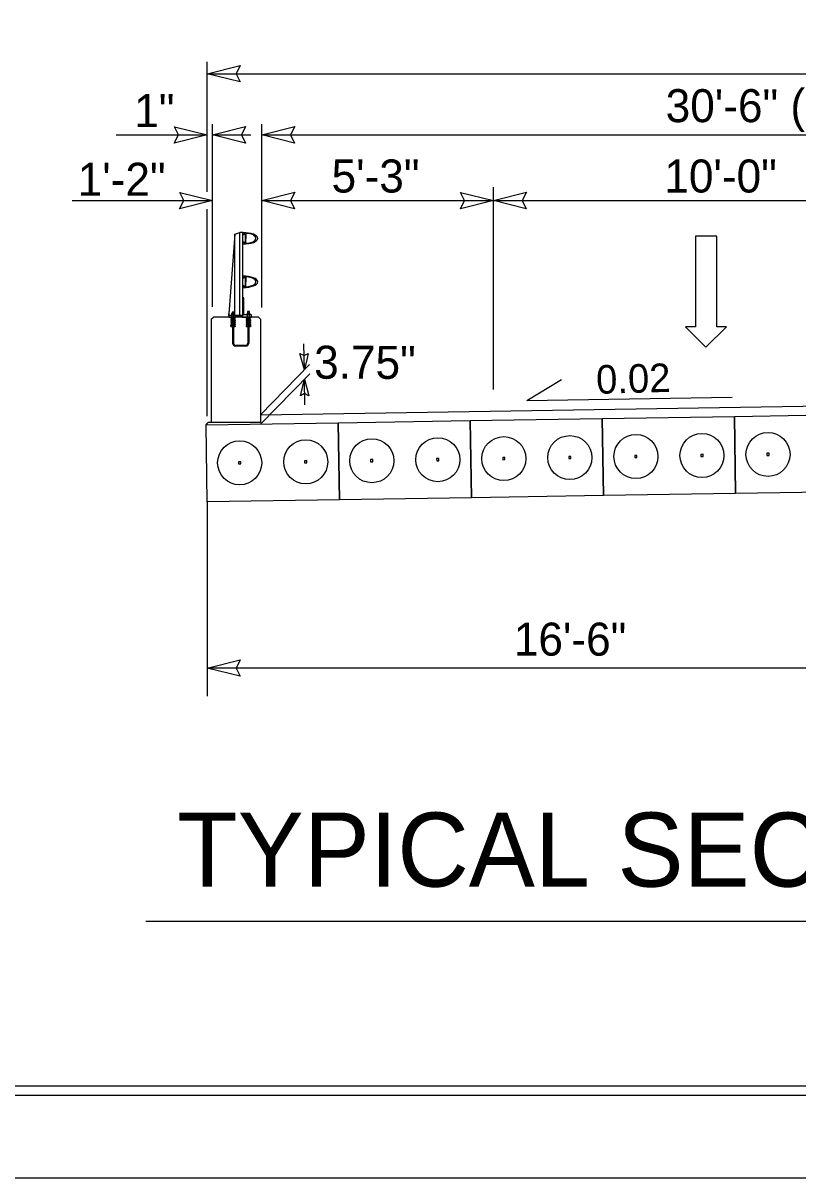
# Model space of a CAD drawing. Extents: x 573980 to 574178, y -53449 to -53334.
# Drawn here: x 574063.55 to 574085.55, y -53449.04 to -53416.26 of the extents above; entities that cross this region are included whole.
import ezdxf

# ---------------------------------------------------------------- set-up
doc = ezdxf.new("R2010")
doc.units = 0
for name, color, linetype in [('Old_Level_1', 7, 'Continuous'), ('Old_Level_11', 7, 'Continuous'), ('Old_Level_3', 7, 'Continuous'), ('Prop Dimension Text', 7, 'Continuous'), ('Prop Lane Arrow CELL', 7, 'Continuous'), ('Sheet Plot Border Inside CELL', 7, 'Continuous'), ('Sheet Plot Border Outside CELL', 7, 'Continuous'), ('Sheet Typical CELL', 7, 'Continuous'), ('Typical Arrow Superelevation CELL', 7, 'Continuous'), ('Typical Berm Information CELL', 7, 'Continuous'), ('Typical Bridge Rail Two Bar CELL', 7, 'Continuous'), ('Typical Terminator CELL', 7, 'Continuous')]:
    doc.layers.add(name, color=color, linetype=linetype)

# ---------------------------------------------------------------- blocks, each defined once
blk = doc.blocks.new('TERMINATOR')
at = {"layer": 'Typical Terminator CELL'}
blk.add_lwpolyline([(-0.469, 0.081), (0, 0), (-0.471, -0.083), (-0.411, 0)], close=True, dxfattribs=at)
blk = doc.blocks.new('Lane Arrow Through')
at = {"layer": 'Prop Lane Arrow CELL'}
for p, q in [((-3.15, 1.6), (-3.15, 3.1)), ((-3.15, 3.1), (0, 0)), ((-17.15, 1.6), (-3.15, 1.6)), ((-17.15, -1.7), (-17.15, 1.6)), ((0, 0), (-3.15, -3.2)), ((-3.15, -1.7), (-17.15, -1.7)), ((-3.15, -3.2), (-3.15, -1.7))]:
    blk.add_line(p, q, dxfattribs=at)

msp = doc.modelspace()

# ---------------------------------------------------------------- linework, layer by layer
at = {"layer": 'Old_Level_1'}
for p, q in [((574070.29, -53427.378), (574108.44, -53426.767)), ((574083.745, -53427.423), (574087.495, -53427.363)), ((574068.747, -53427.663), (574072.497, -53427.603)), ((574068.782, -53429.85), (574068.747, -53427.663)), ((574072.497, -53427.603), (574076.246, -53427.543)), ((574072.497, -53427.603), (574072.532, -53429.79)), ((574072.532, -53429.79), (574072.497, -53427.603)), ((574076.246, -53427.543), (574079.996, -53427.483)), ((574076.246, -53427.543), (574076.281, -53429.73)), ((574076.281, -53429.73), (574076.246, -53427.543)), ((574079.996, -53427.483), (574083.745, -53427.423)), ((574079.996, -53427.483), (574080.031, -53429.67)), ((574080.031, -53429.67), (574079.996, -53427.483)), ((574083.745, -53427.423), (574083.78, -53429.61)), ((574083.78, -53429.61), (574083.745, -53427.423)), ((574069.702, -53428.71), (574069.669, -53428.71)), ((574069.669, -53428.71), (574069.67, -53428.772)), ((574069.731, -53428.709), (574069.702, -53428.71)), ((574069.732, -53428.771), (574069.731, -53428.709)), ((574071.576, -53428.68), (574071.544, -53428.68)), ((574071.544, -53428.68), (574071.545, -53428.742)), ((574071.606, -53428.679), (574071.576, -53428.68)), ((574071.607, -53428.741), (574071.606, -53428.679)), ((574073.451, -53428.65), (574073.419, -53428.65)), ((574073.419, -53428.65), (574073.42, -53428.712)), ((574073.42, -53428.712), (574073.482, -53428.711)), ((574073.481, -53428.649), (574073.451, -53428.65)), ((574073.482, -53428.711), (574073.481, -53428.649)), ((574075.326, -53428.62), (574075.294, -53428.62)), ((574075.294, -53428.62), (574075.295, -53428.682)), ((574075.295, -53428.682), (574075.357, -53428.681)), ((574075.356, -53428.619), (574075.326, -53428.62)), ((574075.357, -53428.681), (574075.356, -53428.619)), ((574077.201, -53428.59), (574077.168, -53428.59)), ((574077.168, -53428.59), (574077.169, -53428.652)), ((574077.169, -53428.652), (574077.231, -53428.651)), ((574077.23, -53428.589), (574077.201, -53428.59)), ((574077.231, -53428.651), (574077.23, -53428.589)), ((574079.075, -53428.56), (574079.043, -53428.56)), ((574079.043, -53428.56), (574079.044, -53428.622)), ((574079.044, -53428.622), (574079.106, -53428.621)), ((574079.105, -53428.559), (574079.075, -53428.56)), ((574079.106, -53428.621), (574079.105, -53428.559)), ((574080.95, -53428.53), (574080.918, -53428.53)), ((574080.918, -53428.53), (574080.919, -53428.592)), ((574080.919, -53428.592), (574080.981, -53428.591)), ((574080.98, -53428.529), (574080.95, -53428.53)), ((574080.981, -53428.591), (574080.98, -53428.529)), ((574082.825, -53428.5), (574082.793, -53428.5)), ((574082.793, -53428.5), (574082.794, -53428.562)), ((574082.794, -53428.562), (574082.856, -53428.561)), ((574082.855, -53428.499), (574082.825, -53428.5)), ((574082.856, -53428.561), (574082.855, -53428.499)), ((574084.7, -53428.47), (574084.668, -53428.47)), ((574084.668, -53428.47), (574084.669, -53428.532)), ((574084.669, -53428.532), (574084.73, -53428.531)), ((574084.729, -53428.469), (574084.7, -53428.47)), ((574084.73, -53428.531), (574084.729, -53428.469)), ((574069.67, -53428.772), (574069.732, -53428.771)), ((574071.545, -53428.742), (574071.607, -53428.741)), ((574080.031, -53429.67), (574076.281, -53429.73)), ((574083.78, -53429.61), (574080.031, -53429.67)), ((574087.53, -53429.55), (574083.78, -53429.61)), ((574072.532, -53429.79), (574068.782, -53429.85)), ((574076.281, -53429.73), (574072.532, -53429.79)), ((574067.039, -53441.751), (574110.919, -53441.751))]:
    msp.add_line(p, q, dxfattribs=at)
for centre in [(574073.452, -53428.682), (574075.326, -53428.652), (574077.201, -53428.622), (574079.076, -53428.592), (574080.951, -53428.562), (574082.825, -53428.532), (574084.7, -53428.502), (574069.702, -53428.742), (574071.577, -53428.712)]:
    msp.add_circle(centre, 0.625, dxfattribs=at)
at = {"layer": 'Prop Dimension Text'}
for p, q in [((574068.782, -53421.051), (574068.782, -53417.355)), ((574068.782, -53417.697), (574110.032, -53417.697)), ((574068.932, -53424.312), (574068.932, -53419.126)), ((574070.33, -53424.334), (574070.33, -53419.126)), ((574066.198, -53419.434), (574068.782, -53419.434)), ((574068.932, -53419.434), (574070.018, -53419.434)), ((574070.33, -53419.434), (574108.485, -53419.434)), ((574076.903, -53426.661), (574076.903, -53420.92)), ((574064.951, -53421.299), (574068.932, -53421.299)), ((574070.33, -53421.299), (574108.485, -53421.299)), ((574068.782, -53427.421), (574068.782, -53421.545)), ((574071.538, -53426.103), (574071.526, -53425.367)), ((574070.29, -53427.378), (574071.685, -53425.953)), ((574070.295, -53427.639), (574071.689, -53426.214)), ((574071.554, -53427.098), (574071.542, -53426.368)), ((574068.782, -53429.85), (574068.782, -53435.367)), ((574089.403, -53434.565), (574068.782, -53434.565))]:
    msp.add_line(p, q, dxfattribs=at)
at = {"layer": 'Sheet Plot Border Inside CELL'}
msp.add_lwpolyline([(574155.747, -53336.331), (573981.441, -53336.331), (573981.441, -53446.688), (574155.747, -53446.688)], close=True, dxfattribs=at)
at = {"layer": 'Sheet Plot Border Outside CELL'}
msp.add_lwpolyline([(574156.218, -53333.982), (573980.081, -53333.982), (573980.081, -53449.036), (574156.218, -53449.036)], close=True, dxfattribs=at)
at = {"layer": 'Sheet Typical CELL'}
msp.add_lwpolyline([(574154.44, -53336.597), (573997.548, -53336.597), (573997.548, -53446.421), (574154.44, -53446.421)], close=True, dxfattribs=at)
at = {"layer": 'Typical Arrow Superelevation CELL'}
for q in [(574078.835, -53426.38), (574083.68, -53426.875)]:
    msp.add_line((574077.854, -53426.968), q, dxfattribs=at)
at = {"layer": 'Typical Bridge Rail Two Bar CELL'}
for p, q in [((574069.56, -53422.249), (574069.396, -53424.51)), ((574069.56, -53422.249), (574069.702, -53422.203)), ((574069.56, -53424.557), (574069.56, -53422.249)), ((574069.796, -53422.203), (574069.702, -53422.203)), ((574069.702, -53424.557), (574069.702, -53422.203)), ((574069.796, -53424.557), (574069.796, -53422.203)), ((574069.875, -53422.242), (574069.875, -53422.37)), ((574069.875, -53422.498), (574069.875, -53422.37)), ((574069.56, -53423.33), (574069.555, -53423.33)), ((574069.875, -53423.476), (574069.875, -53423.604)), ((574069.875, -53423.731), (574069.875, -53423.604)), ((574069.4, -53424.484), (574069.4, -53424.443)), ((574069.977, -53424.45), (574069.923, -53424.45)), ((574069.923, -53424.45), (574069.923, -53424.494)), ((574069.977, -53424.494), (574069.977, -53424.45)), ((574068.897, -53424.665), (574068.958, -53424.604)), ((574068.897, -53424.665), (574068.897, -53427.596)), ((574070.234, -53424.604), (574068.958, -53424.604)), ((574069.396, -53424.557), (574069.396, -53424.51)), ((574069.575, -53424.65), (574069.45, -53424.65)), ((574069.575, -53424.663), (574069.45, -53424.663)), ((574069.502, -53424.705), (574069.45, -53424.705)), ((574069.502, -53424.719), (574069.45, -53424.719)), ((574069.502, -53424.761), (574069.45, -53424.761)), ((574069.502, -53424.775), (574069.45, -53424.775)), ((574069.502, -53424.678), (574069.477, -53424.678)), ((574069.502, -53424.691), (574069.477, -53424.691)), ((574069.502, -53424.733), (574069.477, -53424.733)), ((574069.502, -53424.747), (574069.477, -53424.747)), ((574069.486, -53424.661), (574069.486, -53424.557)), ((574069.541, -53424.462), (574069.487, -53424.462)), ((574069.487, -53424.462), (574069.487, -53424.506)), ((574069.523, -53424.677), (574069.502, -53424.677)), ((574069.502, -53424.677), (574069.502, -53425.341)), ((574069.523, -53424.677), (574069.523, -53425.341)), ((574069.547, -53424.678), (574069.523, -53424.678)), ((574069.547, -53424.691), (574069.523, -53424.691)), ((574069.575, -53424.705), (574069.523, -53424.705)), ((574069.575, -53424.719), (574069.523, -53424.719)), ((574069.547, -53424.733), (574069.523, -53424.733)), ((574069.547, -53424.747), (574069.523, -53424.747)), ((574069.575, -53424.761), (574069.523, -53424.761)), ((574069.575, -53424.775), (574069.523, -53424.775)), ((574069.54, -53424.661), (574069.54, -53424.557)), ((574069.541, -53424.506), (574069.541, -53424.462)), ((574070.011, -53424.65), (574069.885, -53424.65)), ((574070.011, -53424.663), (574069.885, -53424.663)), ((574069.938, -53424.705), (574069.885, -53424.705)), ((574069.938, -53424.719), (574069.885, -53424.719)), ((574069.938, -53424.761), (574069.885, -53424.761)), ((574069.938, -53424.775), (574069.885, -53424.775)), ((574069.938, -53424.678), (574069.913, -53424.678)), ((574069.938, -53424.691), (574069.913, -53424.691)), ((574069.938, -53424.733), (574069.913, -53424.733)), ((574069.938, -53424.747), (574069.913, -53424.747)), ((574069.92, -53424.65), (574069.92, -53424.545)), ((574069.938, -53424.677), (574069.938, -53425.341)), ((574069.959, -53424.678), (574069.938, -53424.678)), ((574069.959, -53424.677), (574069.959, -53425.341)), ((574069.983, -53424.678), (574069.959, -53424.678)), ((574069.983, -53424.691), (574069.959, -53424.691)), ((574070.011, -53424.705), (574069.959, -53424.705)), ((574070.011, -53424.719), (574069.959, -53424.719)), ((574069.983, -53424.733), (574069.959, -53424.733)), ((574069.983, -53424.747), (574069.959, -53424.747)), ((574070.011, -53424.761), (574069.959, -53424.761)), ((574070.011, -53424.775), (574069.959, -53424.775)), ((574069.979, -53424.65), (574069.979, -53424.545)), ((574070.234, -53424.604), (574070.295, -53424.665)), ((574070.295, -53424.665), (574070.295, -53427.596)), ((574069.502, -53424.816), (574069.45, -53424.816)), ((574069.502, -53424.83), (574069.45, -53424.83)), ((574069.502, -53424.872), (574069.45, -53424.872)), ((574069.502, -53424.885), (574069.45, -53424.885)), ((574069.502, -53424.789), (574069.477, -53424.789)), ((574069.502, -53424.802), (574069.477, -53424.802)), ((574069.502, -53424.844), (574069.477, -53424.844)), ((574069.502, -53424.858), (574069.477, -53424.858)), ((574069.547, -53424.789), (574069.523, -53424.789)), ((574069.547, -53424.802), (574069.523, -53424.802)), ((574069.575, -53424.816), (574069.523, -53424.816)), ((574069.575, -53424.83), (574069.523, -53424.83)), ((574069.547, -53424.844), (574069.523, -53424.844)), ((574069.547, -53424.858), (574069.523, -53424.858)), ((574069.575, -53424.872), (574069.523, -53424.872)), ((574069.575, -53424.885), (574069.523, -53424.885)), ((574069.938, -53424.816), (574069.885, -53424.816)), ((574069.938, -53424.83), (574069.885, -53424.83)), ((574069.938, -53424.872), (574069.885, -53424.872)), ((574069.938, -53424.885), (574069.885, -53424.885)), ((574069.938, -53424.789), (574069.913, -53424.789)), ((574069.938, -53424.802), (574069.913, -53424.802)), ((574069.938, -53424.844), (574069.913, -53424.844)), ((574069.938, -53424.858), (574069.913, -53424.858)), ((574069.983, -53424.789), (574069.959, -53424.789)), ((574069.983, -53424.802), (574069.959, -53424.802)), ((574070.011, -53424.816), (574069.959, -53424.816)), ((574070.011, -53424.83), (574069.959, -53424.83)), ((574069.983, -53424.844), (574069.959, -53424.844)), ((574069.983, -53424.858), (574069.959, -53424.858)), ((574070.011, -53424.872), (574069.959, -53424.872)), ((574070.011, -53424.885), (574069.959, -53424.885)), ((574069.871, -53425.407), (574069.59, -53425.407)), ((574069.871, -53425.428), (574069.59, -53425.428)), ((574068.747, -53427.663), (574068.808, -53427.596)), ((574068.909, -53427.596), (574068.808, -53427.596)), ((574070.295, -53427.596), (574068.909, -53427.596))]:
    msp.add_line(p, q, dxfattribs=at)
for points in [[(574069.796, -53422.533), (574069.796, -53422.472), (574069.822, -53422.472), (574069.822, -53422.482), (574069.819, -53422.482), (574069.819, -53422.507), (574069.86, -53422.507), (574069.865, -53422.468), (574069.865, -53422.37), (574069.865, -53422.271), (574069.86, -53422.232), (574069.819, -53422.232), (574069.819, -53422.257), (574069.822, -53422.257), (574069.822, -53422.268), (574069.796, -53422.268), (574069.796, -53422.206)], [(574069.796, -53423.767), (574069.796, -53423.706), (574069.822, -53423.706), (574069.822, -53423.716), (574069.819, -53423.716), (574069.819, -53423.741), (574069.86, -53423.741), (574069.865, -53423.702), (574069.865, -53423.604), (574069.865, -53423.505), (574069.86, -53423.466), (574069.819, -53423.466), (574069.819, -53423.491), (574069.822, -53423.491), (574069.822, -53423.502), (574069.796, -53423.502), (574069.796, -53423.441)], [(574070.038, -53424.604), (574070.038, -53424.545), (574069.82, -53424.545), (574069.82, -53424.062), (574069.796, -53424.062), (574069.796, -53424.557), (574069.407, -53424.557), (574069.407, -53424.522), (574069.396, -53424.522), (574069.396, -53424.604), (574069.583, -53424.604), (574069.583, -53424.572), (574069.773, -53424.572), (574069.773, -53424.604), (574070.038, -53424.604)], [(574069.45, -53424.65), (574069.45, -53424.663), (574069.477, -53424.678), (574069.477, -53424.691), (574069.45, -53424.705), (574069.45, -53424.719), (574069.477, -53424.733), (574069.477, -53424.747), (574069.45, -53424.761), (574069.45, -53424.775), (574069.477, -53424.789), (574069.477, -53424.802), (574069.45, -53424.816), (574069.45, -53424.83), (574069.477, -53424.844), (574069.477, -53424.858), (574069.45, -53424.872), (574069.45, -53424.885)], [(574069.567, -53424.558), (574069.567, -53424.547), (574069.514, -53424.547), (574069.46, -53424.547), (574069.46, -53424.558)], [(574069.553, -53424.547), (574069.553, -53424.513), (574069.547, -53424.506), (574069.481, -53424.506), (574069.474, -53424.513), (574069.474, -53424.547), (574069.553, -53424.547), (574069.527, -53424.547), (574069.527, -53424.513), (574069.534, -53424.506), (574069.527, -53424.513), (574069.521, -53424.506), (574069.507, -53424.506), (574069.5, -53424.513), (574069.5, -53424.547), (574069.5, -53424.513), (574069.494, -53424.506)], [(574069.575, -53424.65), (574069.575, -53424.663), (574069.548, -53424.678), (574069.548, -53424.691), (574069.575, -53424.705), (574069.575, -53424.719), (574069.548, -53424.733), (574069.548, -53424.747), (574069.575, -53424.761), (574069.575, -53424.775), (574069.548, -53424.789), (574069.548, -53424.802), (574069.575, -53424.816), (574069.575, -53424.83), (574069.548, -53424.844), (574069.548, -53424.858), (574069.575, -53424.872), (574069.575, -53424.885)], [(574069.885, -53424.65), (574069.885, -53424.663), (574069.913, -53424.678), (574069.913, -53424.691), (574069.885, -53424.705), (574069.885, -53424.719), (574069.913, -53424.733), (574069.913, -53424.747), (574069.885, -53424.761), (574069.885, -53424.775), (574069.913, -53424.789), (574069.913, -53424.802), (574069.885, -53424.816), (574069.885, -53424.83), (574069.913, -53424.844), (574069.913, -53424.858), (574069.885, -53424.872), (574069.885, -53424.885)], [(574070.005, -53424.546), (574070.005, -53424.535), (574069.951, -53424.535), (574069.897, -53424.535), (574069.897, -53424.546)], [(574069.99, -53424.535), (574069.99, -53424.501), (574069.983, -53424.494), (574069.917, -53424.494), (574069.91, -53424.501), (574069.91, -53424.535), (574069.99, -53424.535), (574069.963, -53424.535), (574069.963, -53424.501), (574069.97, -53424.494), (574069.963, -53424.501), (574069.957, -53424.494), (574069.943, -53424.494), (574069.937, -53424.501), (574069.937, -53424.535), (574069.937, -53424.501), (574069.93, -53424.494)], [(574070.011, -53424.65), (574070.011, -53424.663), (574069.983, -53424.678), (574069.983, -53424.691), (574070.011, -53424.705), (574070.011, -53424.719), (574069.983, -53424.733), (574069.983, -53424.747), (574070.011, -53424.761), (574070.011, -53424.775), (574069.983, -53424.789), (574069.983, -53424.802), (574070.011, -53424.816), (574070.011, -53424.83), (574069.983, -53424.844), (574069.983, -53424.858), (574070.011, -53424.872), (574070.011, -53424.885)]]:
    msp.add_lwpolyline(points, dxfattribs=at)
for centre in [(574069.461, -53424.851), (574070, -53424.851)]:
    msp.add_circle(centre, 0.0104, dxfattribs=at)
for centre, radius, start, end in [((574069.885, -53422.242), 0.00979, 90, 180), ((574069.885, -53422.498), 0.00979, 180, 270), ((574069.885, -53423.476), 0.00979, 90, 180), ((574069.885, -53423.732), 0.00979, 180, 270), ((574069.59, -53425.341), 0.0876, 180, 270), ((574069.59, -53425.341), 0.0667, 180, 270), ((574069.871, -53425.341), 0.0667, 270, 0), ((574069.871, -53425.341), 0.0876, 270, 0)]:
    msp.add_arc(centre, radius, start, end, dxfattribs=at)
for centre, major_axis, ratio, start_param, end_param in [((574069.796, -53422.37), (0.418, 0), 0.39036, 6.282787, 7.853967), ((574069.796, -53422.37), (0.418, 0), 0.39036, 4.712404, 6.282787), ((574069.885, -53422.37), (0.278, 0), 0.495501, 6.282718, 7.853881), ((574069.885, -53422.37), (0.278, 0), 0.495501, 4.712489, 6.282718), ((574069.796, -53423.604), (0.418, 0), 0.39036, 6.282787, 7.853967), ((574069.885, -53423.604), (0.278, 0), 0.495501, 6.282718, 7.853881), ((574069.796, -53423.604), (0.418, 0), 0.39036, 4.712404, 6.282787), ((574069.885, -53423.604), (0.278, 0), 0.495501, 4.712489, 6.282718)]:
    msp.add_ellipse(centre, major_axis=major_axis, ratio=ratio, start_param=start_param, end_param=end_param, dxfattribs=at)

# ---------------------------------------------------------------- block references
at = {"layer": 'Old_Level_1', "xscale": 0.18374999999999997, "yscale": -0.18374999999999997, "rotation": -90.00000000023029}
msp.add_blockref('Lane Arrow Through', (574082.931, -53425.457), dxfattribs=at)
at = {"layer": 'Old_Level_11'}
for p, xscale, yscale, rotation in [((574068.782, -53417.697), 1.9883351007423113, 2.8538812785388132, 179.9999999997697), ((574068.782, -53419.434), 1.9883351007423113, 2.8538812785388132, -2.3029191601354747e-10), ((574068.932, -53419.434), 1.9883351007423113, 2.8538812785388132, 179.9999999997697), ((574070.33, -53419.434), 1.9883351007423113, 2.8538812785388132, 179.9999999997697), ((574068.932, -53421.299), 1.9883351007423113, 2.8538812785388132, -2.3029191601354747e-10), ((574070.33, -53421.299), 1.9883351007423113, 2.8538812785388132, 179.9999999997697), ((574076.903, -53421.299), 1.9883351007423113, 2.8538812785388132, -2.3029191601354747e-10), ((574076.903, -53421.299), 1.9883351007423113, 2.8538812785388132, 179.9999999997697), ((574071.538, -53426.103), 0.9941675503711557, 1.4269406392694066, -89.08334574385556), ((574071.542, -53426.368), 0.9941675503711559, 1.4269406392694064, 90.67371510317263), ((574068.782, -53434.565), 1.9883351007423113, 2.8538812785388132, 179.9999999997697)]:
    msp.add_blockref('TERMINATOR', p, dxfattribs=dict(at, xscale=xscale, yscale=yscale, rotation=rotation))

# ---------------------------------------------------------------- texts
at = {"layer": 'Old_Level_3'}
msp.add_text('TYPICAL SECTION ON BRIDGE', height=2.1024, dxfattribs=at).set_placement((574067.928, -53440.77))
at = {"layer": 'Prop Dimension Text'}
for s, rotation, p in [('30\'-6" (CLEAR ROADWAY)', 360, (574081.795, -53419.073)), ('1"', 360, (574066.709, -53419.213)), ('5\'-3"', 360, (574072.311, -53421.069)), ('10\'-0"', 360, (574081.757, -53421.069)), ('1\'-2"', 360, (574065.104, -53421.161)), ('3.75"', 359.8485, (574071.815, -53426.353)), ('16\'-6"', 360, (574077.485, -53434.214))]:
    msp.add_text(s, height=0.9375, rotation=rotation, dxfattribs=at).set_placement(p)
at = {"layer": 'Typical Berm Information CELL'}
msp.add_text('0.02', height=0.8113, rotation=1.5793, dxfattribs=at).set_placement((574079.831, -53426.784))

doc.saveas('drawing.dxf')
